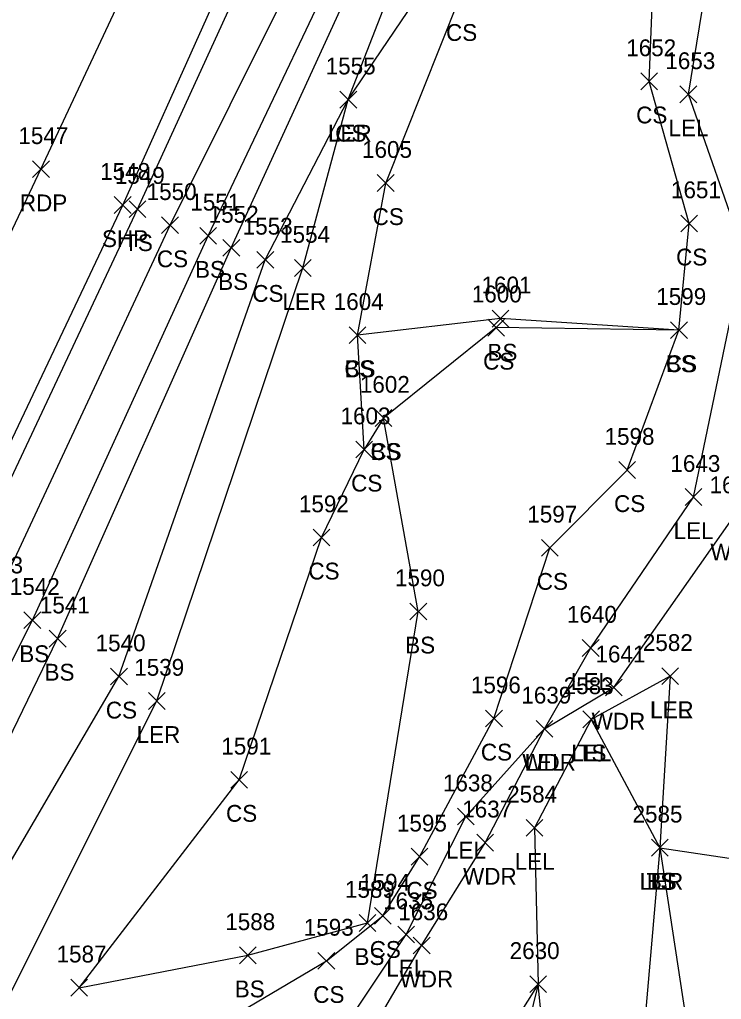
# Model space of a CAD drawing. Extents: x 1483143 to 1488182, y 802902 to 807581.
# Drawn here: x 1487627.8 to 1487711.4, y 805857.9 to 805974.5 of the extents above; entities that cross this region are included whole.
import ezdxf

# ---------------------------------------------------------------- set-up
doc = ezdxf.new("R2010")
doc.units = 0
for name, color, linetype in [('L_A', 7, 'Continuous'), ('L_I', 7, 'Continuous'), ('L_TIC', 7, 'Continuous'), ('LARO', 7, 'Continuous'), ('LAWA', 7, 'Continuous'), ('LELB', 7, 'Continuous'), ('P_A', 7, 'Continuous'), ('P_I', 7, 'Continuous'), ('P_TIC', 7, 'Continuous'), ('PET', 7, 'Continuous'), ('PSP', 7, 'Continuous')]:
    doc.layers.add(name, color=color, linetype=linetype)

msp = doc.modelspace()

# ---------------------------------------------------------------- linework, layer by layer
at = {"layer": 'L_TIC'}
for points in [[(1487701.79, 805966.14), (1487703.79, 805968.14)], [(1487703.79, 805966.14), (1487701.79, 805968.14)], [(1487706.45, 805964.6), (1487708.45, 805966.6)], [(1487708.45, 805964.6), (1487706.45, 805966.6)], [(1487665.95, 805963.97), (1487667.95, 805965.97)], [(1487667.95, 805963.97), (1487665.95, 805965.97)], [(1487665.95, 805963.97), (1487667.95, 805965.97)], [(1487667.95, 805963.97), (1487665.95, 805965.97)], [(1487670.41, 805954.04), (1487672.41, 805956.04)], [(1487672.41, 805954.04), (1487670.41, 805956.04)], [(1487640.85, 805950.94), (1487642.85, 805952.94)], [(1487642.85, 805950.94), (1487640.85, 805952.94)], [(1487706.55, 805949.23), (1487708.55, 805951.23)], [(1487708.55, 805949.23), (1487706.55, 805951.23)], [(1487644.72, 805949.02), (1487646.72, 805951.02)], [(1487646.72, 805949.02), (1487644.72, 805951.02)], [(1487649.26, 805947.76), (1487651.26, 805949.76)], [(1487651.26, 805947.76), (1487649.26, 805949.76)], [(1487652.02, 805946.32), (1487654.02, 805948.32)], [(1487654.02, 805946.32), (1487652.02, 805948.32)], [(1487656.07, 805944.9), (1487658.07, 805946.9)], [(1487658.07, 805944.9), (1487656.07, 805946.9)], [(1487660.53, 805943.93), (1487662.53, 805945.93)], [(1487662.53, 805943.93), (1487660.53, 805945.93)], [(1487684.07, 805937.9), (1487686.07, 805939.9)], [(1487686.07, 805937.9), (1487684.07, 805939.9)], [(1487683.57, 805936.83), (1487685.57, 805938.83)], [(1487685.57, 805936.83), (1487683.57, 805938.83)], [(1487705.33, 805936.53), (1487707.33, 805938.53)], [(1487707.33, 805936.53), (1487705.33, 805938.53)], [(1487705.33, 805936.53), (1487707.33, 805938.53)], [(1487707.33, 805936.53), (1487705.33, 805938.53)], [(1487705.33, 805936.53), (1487707.33, 805938.53)], [(1487707.33, 805936.53), (1487705.33, 805938.53)], [(1487667.04, 805935.93), (1487669.04, 805937.93)], [(1487669.04, 805935.93), (1487667.04, 805937.93)], [(1487667.04, 805935.93), (1487669.04, 805937.93)], [(1487669.04, 805935.93), (1487667.04, 805937.93)], [(1487670.15, 805926.07), (1487672.15, 805928.07)], [(1487672.15, 805926.07), (1487670.15, 805928.07)], [(1487670.15, 805926.07), (1487672.15, 805928.07)], [(1487672.15, 805926.07), (1487670.15, 805928.07)], [(1487667.85, 805922.32), (1487669.85, 805924.32)], [(1487669.85, 805922.32), (1487667.85, 805924.32)], [(1487667.85, 805922.32), (1487669.85, 805924.32)], [(1487669.85, 805922.32), (1487667.85, 805924.32)], [(1487699.16, 805919.88), (1487701.16, 805921.88)], [(1487701.16, 805919.88), (1487699.16, 805921.88)], [(1487707.05, 805916.66), (1487709.05, 805918.66)], [(1487709.05, 805916.66), (1487707.05, 805918.66)], [(1487662.76, 805911.85), (1487664.76, 805913.85)], [(1487664.76, 805911.85), (1487662.76, 805913.85)], [(1487689.96, 805910.62), (1487691.96, 805912.62)], [(1487691.96, 805910.62), (1487689.96, 805912.62)], [(1487674.29, 805903.04), (1487676.29, 805905.04)], [(1487676.29, 805903.04), (1487674.29, 805905.04)], [(1487628.33, 805902.01), (1487630.33, 805904.01)], [(1487630.33, 805902.01), (1487628.33, 805904.01)], [(1487631.34, 805899.81), (1487633.34, 805901.81)], [(1487633.34, 805899.81), (1487631.34, 805901.81)], [(1487694.82, 805898.7), (1487696.82, 805900.7)], [(1487696.82, 805898.7), (1487694.82, 805900.7)], [(1487638.64, 805895.3), (1487640.64, 805897.3)], [(1487640.64, 805895.3), (1487638.64, 805897.3)], [(1487704.29, 805895.34), (1487706.29, 805897.34)], [(1487706.29, 805895.34), (1487704.29, 805897.34)], [(1487704.29, 805895.34), (1487706.29, 805897.34)], [(1487706.29, 805895.34), (1487704.29, 805897.34)], [(1487697.57, 805893.98), (1487699.57, 805895.98)], [(1487699.57, 805893.98), (1487697.57, 805895.98)], [(1487643.16, 805892.39), (1487645.16, 805894.39)], [(1487645.16, 805892.39), (1487643.16, 805894.39)], [(1487683.3, 805890.3), (1487685.3, 805892.3)], [(1487685.3, 805890.3), (1487683.3, 805892.3)], [(1487694.87, 805890.2), (1487696.87, 805892.2)], [(1487696.87, 805890.2), (1487694.87, 805892.2)], [(1487694.87, 805890.2), (1487696.87, 805892.2)], [(1487696.87, 805890.2), (1487694.87, 805892.2)], [(1487689.31, 805889.08), (1487691.31, 805891.08)], [(1487691.31, 805889.08), (1487689.31, 805891.08)], [(1487689.31, 805889.08), (1487691.31, 805891.08)], [(1487691.31, 805889.08), (1487689.31, 805891.08)], [(1487652.95, 805883.01), (1487654.95, 805885.01)], [(1487654.95, 805883.01), (1487652.95, 805885.01)], [(1487679.96, 805878.63), (1487681.96, 805880.63)], [(1487681.96, 805878.63), (1487679.96, 805880.63)], [(1487688.13, 805877.29), (1487690.13, 805879.29)], [(1487690.13, 805877.29), (1487688.13, 805879.29)], [(1487682.26, 805875.52), (1487684.26, 805877.52)], [(1487684.26, 805875.52), (1487682.26, 805877.52)], [(1487703.06, 805874.92), (1487705.06, 805876.92)], [(1487705.06, 805874.92), (1487703.06, 805876.92)], [(1487703.06, 805874.92), (1487705.06, 805876.92)], [(1487705.06, 805874.92), (1487703.06, 805876.92)], [(1487703.06, 805874.92), (1487705.06, 805876.92)], [(1487705.06, 805874.92), (1487703.06, 805876.92)], [(1487674.43, 805873.85), (1487676.43, 805875.85)], [(1487676.43, 805873.85), (1487674.43, 805875.85)], [(1487670.06, 805866.81), (1487672.06, 805868.81)], [(1487672.06, 805866.81), (1487670.06, 805868.81)], [(1487668.25, 805865.96), (1487670.25, 805867.96)], [(1487670.25, 805865.96), (1487668.25, 805867.96)], [(1487672.84, 805864.59), (1487674.84, 805866.59)], [(1487674.84, 805864.59), (1487672.84, 805866.59)], [(1487674.69, 805863.29), (1487676.69, 805865.29)], [(1487676.69, 805863.29), (1487674.69, 805865.29)], [(1487653.99, 805862.11), (1487655.99, 805864.11)], [(1487655.99, 805862.11), (1487653.99, 805864.11)], [(1487663.34, 805861.45), (1487665.34, 805863.45)], [(1487665.34, 805861.45), (1487663.34, 805863.45)], [(1487633.9, 805858.26), (1487635.9, 805860.26)], [(1487635.9, 805858.26), (1487633.9, 805860.26)], [(1487633.9, 805858.26), (1487635.9, 805860.26)], [(1487635.9, 805858.26), (1487633.9, 805860.26)], [(1487688.57, 805858.67), (1487690.57, 805860.67)], [(1487690.57, 805858.67), (1487688.57, 805860.67)], [(1487688.57, 805858.67), (1487690.57, 805860.67)], [(1487690.57, 805858.67), (1487688.57, 805860.67)]]:
    msp.add_lwpolyline(points, dxfattribs=at)
at = {"layer": 'LARO'}
for points in [[(1487519.52, 805604.85), (1487528.65, 805619.18), (1487533.33, 805631.91), (1487543.2, 805654.53), (1487555.05, 805678.36), (1487574.29, 805702.91), (1487587.86, 805730.92), (1487594.38, 805745.99), (1487602.81, 805747.66), (1487615.34, 805754.21), (1487619.89, 805765.57), (1487618.06, 805788.02), (1487632.01, 805808.09), (1487647.52, 805827.2), (1487662.05, 805847.87), (1487673.84, 805865.59), (1487680.96, 805879.63), (1487690.31, 805890.08), (1487695.82, 805899.7), (1487708.05, 805917.66), (1487714.11, 805946.66), (1487707.45, 805965.6), (1487711.43, 805989.94)], [(1487515.16, 805650.67), (1487521.68, 805670.54), (1487529.04, 805683.79), (1487537.68, 805691.67), (1487539.17, 805698.49), (1487539.8, 805706.7), (1487559.66, 805737.44), (1487565.81, 805755.37), (1487573.16, 805761.97), (1487578.75, 805774.48), (1487583.53, 805786.84), (1487609.69, 805840.26), (1487624.13, 805853.53), (1487644.16, 805893.39), (1487661.53, 805944.93), (1487666.95, 805964.97), (1487680.31, 805984.75)], [(1487705.29, 805896.34), (1487695.87, 805891.2), (1487689.13, 805878.29), (1487689.57, 805859.67), (1487670.44, 805829.21), (1487659.71, 805823.79), (1487649.08, 805803.93), (1487638.97, 805785.42), (1487633.21, 805776.22), (1487626.14, 805756.53), (1487619.37, 805736.85), (1487617.73, 805704.95), (1487625.22, 805691.16), (1487634.64, 805682.02), (1487622.34, 805673.38), (1487621.2, 805638.86), (1487621.06, 805617.78)], [(1487705.29, 805896.34), (1487704.06, 805875.92), (1487701.89, 805851.18), (1487695.31, 805846.63), (1487693.97, 805826.04), (1487694.06, 805815.15), (1487697.49, 805803.83), (1487704.56, 805795.94), (1487708.81, 805792.59), (1487701.05, 805792.26), (1487694.18, 805794.48), (1487690.59, 805771.57), (1487689.27, 805761.59), (1487692.86, 805752.01), (1487698.86, 805745.28), (1487699.02, 805718.81), (1487691.81, 805707.17), (1487691.68, 805697.79), (1487684.12, 805691.56), (1487666.83, 805689.24), (1487654.3, 805698.63), (1487654.93, 805715.83), (1487638.67, 805718.86)]]:
    msp.add_lwpolyline(points, dxfattribs=at)
at = {"layer": 'LAWA'}
msp.add_lwpolyline([(1487529.09, 805606.14), (1487539.28, 805632.42), (1487550.45, 805657.72), (1487555.05, 805678.36), (1487580.53, 805701.65), (1487594.42, 805727.14), (1487615.34, 805754.21), (1487623.26, 805766.5), (1487630.87, 805783.06), (1487637.96, 805804.22), (1487654.61, 805825.46), (1487661.73, 805840.49), (1487675.69, 805864.29), (1487683.26, 805876.52), (1487690.31, 805890.08), (1487698.57, 805894.98), (1487712.71, 805915.11), (1487715.76, 805935.97), (1487722.85, 805947.47), (1487721.66, 805955.35), (1487715.74, 805966.94), (1487726.15, 805982.46)], dxfattribs=at)
at = {"layer": 'LELB'}
for points in [[(1487406.66, 805485.41), (1487431.45, 805531.24), (1487454.84, 805575.74), (1487473.75, 805612.05), (1487489.43, 805642.37), (1487507.64, 805678.53), (1487524.82, 805711.39), (1487541.86, 805746.09), (1487557.67, 805776.44), (1487575.49, 805812.01), (1487597.52, 805857.93), (1487620.62, 805906.82), (1487641.85, 805951.94), (1487662.18, 805996.35), (1487684.09, 806043.93), (1487694.42, 806066.95), (1487726.58, 806140.7), (1487745.85, 806185.55), (1487769.04, 806237.65), (1487788.58, 806284.85), (1487808.3, 806333.26), (1487827.52, 806379.6), (1487850.09, 806437.73)], [(1487410.04, 805483.24), (1487436.07, 805529.53), (1487459.78, 805575.03), (1487477.42, 805609.67), (1487492.45, 805639.09), (1487509.86, 805677.27), (1487528.68, 805708.85), (1487545.3, 805744.17), (1487561.79, 805774.32), (1487579.7, 805810.21), (1487602.04, 805856.31), (1487624.97, 805905.57), (1487645.72, 805950.02), (1487667.21, 805993.1), (1487687.16, 806043.23), (1487699.2, 806065.16), (1487730.65, 806138.87), (1487749.96, 806183.58), (1487772.93, 806235.17), (1487792.36, 806283.08), (1487812.9, 806331.5), (1487831.61, 806378.23), (1487855.61, 806436.65)], [(1487413.83, 805481.53), (1487440.22, 805526.89), (1487464.36, 805572.85), (1487481.71, 805606.55), (1487496.63, 805636.25), (1487514.9, 805673.97), (1487535.8, 805705.94), (1487549.07, 805741.59), (1487566.17, 805772.22), (1487583.99, 805807.69), (1487605.26, 805855.28), (1487629.33, 805903.01), (1487650.26, 805948.76), (1487670.48, 805991.25), (1487690.28, 806041.74), (1487702.22, 806061.37), (1487704.47, 806066.39), (1487735.28, 806136.71), (1487754, 806182.42), (1487776.55, 806233.47), (1487796.75, 806281.41), (1487816.88, 806330.25), (1487835.19, 806376.59), (1487859.78, 806434.97)], [(1487417, 805480.8), (1487442.28, 805525.8), (1487466.47, 805571.82), (1487483.84, 805604.86), (1487498.25, 805635.76), (1487518.24, 805671.86), (1487538.47, 805704.77), (1487552.2, 805739.67), (1487568.17, 805771.84), (1487585.97, 805806.76), (1487609.39, 805853.47), (1487632.34, 805900.81), (1487653.02, 805947.32), (1487672.59, 805990.01), (1487694.92, 806039.27), (1487707.45, 806059.25), (1487710.05, 806064.3), (1487737.97, 806135.43), (1487757.4, 806181.42), (1487778.76, 806231.94), (1487799.97, 806279.97), (1487818.92, 806329.91), (1487837.5, 806376), (1487863.45, 806433.38)], [(1487539.8, 805706.7), (1487554.99, 805738.51), (1487564.78, 805761.24), (1487572.42, 805770.06), (1487590.42, 805804.18), (1487613.31, 805851.36), (1487639.64, 805896.3), (1487657.07, 805945.9), (1487666.95, 805964.97), (1487675.89, 805987.99), (1487698.82, 806037.9), (1487713.56, 806059.8), (1487740.03, 806134.78), (1487759.8, 806179.98), (1487782.43, 806230.23), (1487804.48, 806278.55), (1487821.45, 806329.34), (1487839.66, 806374.66), (1487865.87, 806433.14)], [(1487634.9, 805859.26), (1487653.95, 805884.01), (1487663.76, 805912.85), (1487668.85, 805923.32), (1487668.04, 805936.93), (1487671.41, 805955.04), (1487680.15, 805976.96), (1487690.86, 805995.28), (1487690.86, 805995.28), (1487697.23, 806012.79), (1487721.71, 806030.21), (1487724.95, 806032.99), (1487717.09, 806036.1), (1487721.56, 806049.74)], [(1487632.01, 805808.09), (1487619.24, 805827.81), (1487647.66, 805852.57), (1487664.34, 805862.45), (1487671.06, 805867.81), (1487675.43, 805874.85), (1487684.3, 805891.3), (1487690.96, 805911.62), (1487700.16, 805920.88), (1487706.33, 805937.53), (1487707.55, 805950.23), (1487702.79, 805967.14), (1487703.8, 805992.98), (1487705.2, 806012.67), (1487721.31, 806024.08), (1487727.61, 806022.94), (1487740.06, 806020.89), (1487749.42, 806025.91)], [(1487706.33, 805937.53), (1487685.07, 805938.9), (1487668.04, 805936.93)], [(1487706.33, 805937.53), (1487684.57, 805937.83), (1487671.15, 805927.07), (1487668.85, 805923.32)], [(1487634.9, 805859.26), (1487654.99, 805863.11), (1487669.25, 805866.96), (1487675.29, 805904.04), (1487671.15, 805927.07)], [(1487695.87, 805891.2), (1487704.06, 805875.92), (1487718.72, 805873.74)], [(1487704.06, 805875.92), (1487708.63, 805845.96)], [(1487694.18, 805794.48), (1487693.17, 805806.33), (1487687.93, 805817.69), (1487689.85, 805831.08), (1487691.37, 805841.24), (1487689.57, 805859.67), (1487682.46, 805830.78), (1487680.31, 805810.06), (1487676.2, 805786.76), (1487678.62, 805754.73), (1487686.02, 805754.18), (1487689.27, 805761.59)]]:
    msp.add_lwpolyline(points, dxfattribs=at)
at = {"layer": 'P_TIC'}
for points in [[(1487629.35, 805955.68), (1487631.35, 805957.68)], [(1487631.35, 805955.68), (1487629.35, 805957.68)], [(1487639.09, 805951.42), (1487641.09, 805953.42)], [(1487641.09, 805951.42), (1487639.09, 805953.42)]]:
    msp.add_lwpolyline(points, dxfattribs=at)
at = {"layer": 'PET'}
msp.add_lwpolyline([(1487396.33, 805490.41), (1487421.9, 805537.94), (1487444.13, 805580.16), (1487464.29, 805618.83), (1487479.8, 805648.39), (1487498.08, 805684.27), (1487514.57, 805717.15), (1487530.55, 805749.06), (1487547.16, 805782.47), (1487564.33, 805817.54), (1487585.71, 805863.32), (1487608.89, 805911.38), (1487630.35, 805956.68), (1487651.22, 806001.25), (1487672.63, 806048.33), (1487683.65, 806072.29), (1487715.61, 806144.47), (1487735.35, 806190.47), (1487757.48, 806241.03), (1487777.65, 806289.15), (1487798.25, 806337.46), (1487817.05, 806384.04), (1487839.67, 806441.4)], dxfattribs=at)
at = {"layer": 'PSP'}
msp.add_lwpolyline([(1487405.03, 805486.21), (1487429.8, 805532.42), (1487452.92, 805576.31), (1487472.37, 805613.24), (1487487.86, 805643.29), (1487506.35, 805679.4), (1487523.34, 805712.45), (1487540.38, 805746.64), (1487556.03, 805777.85), (1487573.44, 805813.27), (1487595.34, 805859.04), (1487618.37, 805906.67), (1487640.09, 805952.42), (1487660.18, 805997.21), (1487682.38, 806044.71), (1487693.04, 806068.56), (1487725.12, 806141.19), (1487744.39, 806185.87), (1487766.81, 806238.55), (1487786.8, 806285.64), (1487806.77, 806333.93), (1487825.55, 806380.21), (1487847.81, 806437.56)], dxfattribs=at)

# ---------------------------------------------------------------- texts
at = {"layer": 'L_A'}
for s, p in [('CS', (1487678.59, 805971.96)), ('CS', (1487701.23, 805962.14)), ('LER', (1487664.53, 805959.97)), ('CS', (1487665.39, 805959.97)), ('LEL', (1487705.09, 805960.6)), ('CS', (1487669.85, 805950.04)), ('TS', (1487640.26, 805946.94)), ('CS', (1487644.16, 805945.02)), ('CS', (1487705.99, 805945.23)), ('BS', (1487648.7, 805943.76)), ('BS', (1487651.46, 805942.32)), ('CS', (1487655.52, 805940.9)), ('LER', (1487659.11, 805939.93)), ('BS', (1487683.52, 805933.9)), ('CS', (1487666.48, 805931.93)), ('BS', (1487666.48, 805931.93)), ('CS', (1487683.01, 805932.83)), ('CS', (1487704.77, 805932.53)), ('CS', (1487704.77, 805932.53)), ('BS', (1487704.77, 805932.53)), ('CS', (1487669.59, 805922.07)), ('BS', (1487669.59, 805922.07)), ('CS', (1487667.29, 805918.32)), ('CS', (1487667.29, 805918.32)), ('CS', (1487698.6, 805915.88)), ('LEL', (1487705.69, 805912.66)), ('WDR', (1487710.07, 805910.11)), ('CS', (1487662.2, 805907.85)), ('CS', (1487689.4, 805906.62)), ('BS', (1487673.73, 805899.04)), ('BS', (1487627.77, 805898.01)), ('BS', (1487630.78, 805895.81)), ('LEL', (1487693.46, 805894.7)), ('CS', (1487638.08, 805891.3)), ('LER', (1487702.87, 805891.34)), ('LEL', (1487702.93, 805891.34)), ('WDR', (1487695.93, 805889.98)), ('LER', (1487641.74, 805888.39)), ('CS', (1487682.74, 805886.3)), ('WDR', (1487687.67, 805885.08)), ('LEL', (1487687.95, 805885.08)), ('LEL', (1487693.51, 805886.2)), ('TS', (1487694.28, 805886.2)), ('CS', (1487652.39, 805879.01)), ('LEL', (1487678.59, 805874.63)), ('LEL', (1487686.77, 805873.29)), ('WDR', (1487680.62, 805871.52)), ('LER', (1487701.64, 805870.92)), ('TS', (1487702.47, 805870.92)), ('BS', (1487702.5, 805870.92)), ('CS', (1487673.87, 805869.85)), ('BS', (1487667.69, 805861.96)), ('CS', (1487669.5, 805862.81)), ('LEL', (1487671.48, 805860.59)), ('WDR', (1487673.06, 805859.29)), ('BS', (1487653.43, 805858.11)), ('CS', (1487662.78, 805857.45))]:
    msp.add_text(s, height=2, dxfattribs=at).set_placement(p)
at = {"layer": 'L_I'}
for s, p in [('1652', (1487700.05, 805970.14)), ('1555', (1487664.26, 805967.97)), ('1555', (1487664.26, 805967.97)), ('1653', (1487704.71, 805968.6)), ('1605', (1487668.59, 805958.04)), ('1549', (1487639.15, 805954.94)), ('1550', (1487642.94, 805953.02)), ('1651', (1487705.38, 805953.23)), ('1551', (1487648.14, 805951.76)), ('1552', (1487650.33, 805950.32)), ('1553', (1487654.38, 805948.9)), ('1554', (1487658.83, 805947.93)), ('1601', (1487682.82, 805941.9)), ('1604', (1487665.22, 805939.93)), ('1604', (1487665.22, 805939.93)), ('1600', (1487681.66, 805940.83)), ('1599', (1487703.63, 805940.53)), ('1599', (1487703.63, 805940.53)), ('1599', (1487703.63, 805940.53)), ('1602', (1487668.33, 805930.07)), ('1602', (1487668.33, 805930.07)), ('1603', (1487666.03, 805926.32)), ('1603', (1487666.03, 805926.32)), ('1598', (1487697.47, 805923.88)), ('1643', (1487705.31, 805920.66)), ('1642', (1487709.97, 805918.11)), ('1592', (1487661.07, 805915.85)), ('1597', (1487688.27, 805914.62)), ('1543', (1487622.27, 805908.57)), ('1590', (1487672.51, 805907.04)), ('1542', (1487626.64, 805906.01)), ('1541', (1487630.22, 805903.81)), ('1640', (1487692.99, 805902.7)), ('1540', (1487636.86, 805899.3)), ('2582', (1487702.03, 805899.34)), ('2582', (1487702.03, 805899.34)), ('1641', (1487696.39, 805897.98)), ('1539', (1487641.46, 805896.39)), ('1596', (1487681.55, 805894.3)), ('2583', (1487692.61, 805894.2)), ('2583', (1487692.61, 805894.2)), ('1639', (1487687.56, 805893.08)), ('1639', (1487687.56, 805893.08)), ('1591', (1487651.83, 805887.01)), ('1638', (1487678.22, 805882.63)), ('2584', (1487685.87, 805881.29)), ('1637', (1487680.52, 805879.52)), ('2585', (1487700.8, 805878.92)), ('2585', (1487700.8, 805878.92)), ('2585', (1487700.8, 805878.92)), ('1595', (1487672.74, 805877.85)), ('1589', (1487666.55, 805869.96)), ('1594', (1487668.36, 805870.81)), ('1635', (1487671.1, 805868.59)), ('1636', (1487672.9, 805867.29)), ('1588', (1487652.3, 805866.11)), ('1593', (1487661.65, 805865.45)), ('1587', (1487632.21, 805862.26)), ('1587', (1487632.21, 805862.26)), ('2630', (1487686.17, 805862.67)), ('2630', (1487686.17, 805862.67))]:
    msp.add_text(s, height=2, dxfattribs=at).set_placement(p)
at = {"layer": 'P_A'}
for s, p in [('RDP', (1487627.84, 805951.68)), ('SHP', (1487637.62, 805947.42))]:
    msp.add_text(s, height=2, dxfattribs=at).set_placement(p)
at = {"layer": 'P_I'}
for s, p in [('1547', (1487627.66, 805959.68)), ('1548', (1487637.4, 805955.42))]:
    msp.add_text(s, height=2, dxfattribs=at).set_placement(p)

doc.saveas('drawing.dxf')
